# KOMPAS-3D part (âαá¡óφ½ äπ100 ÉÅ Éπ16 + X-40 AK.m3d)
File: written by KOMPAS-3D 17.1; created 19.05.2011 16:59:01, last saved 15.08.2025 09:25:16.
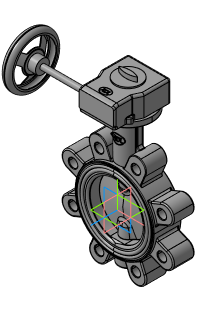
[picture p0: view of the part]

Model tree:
1. Плоскость XY
2. Плоскость ZX
3. Плоскость ZY
4. Ось X
5. Ось Y
6. Ось Z
7. Начало координат
8. Операция без истории:5

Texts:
  Viktor2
